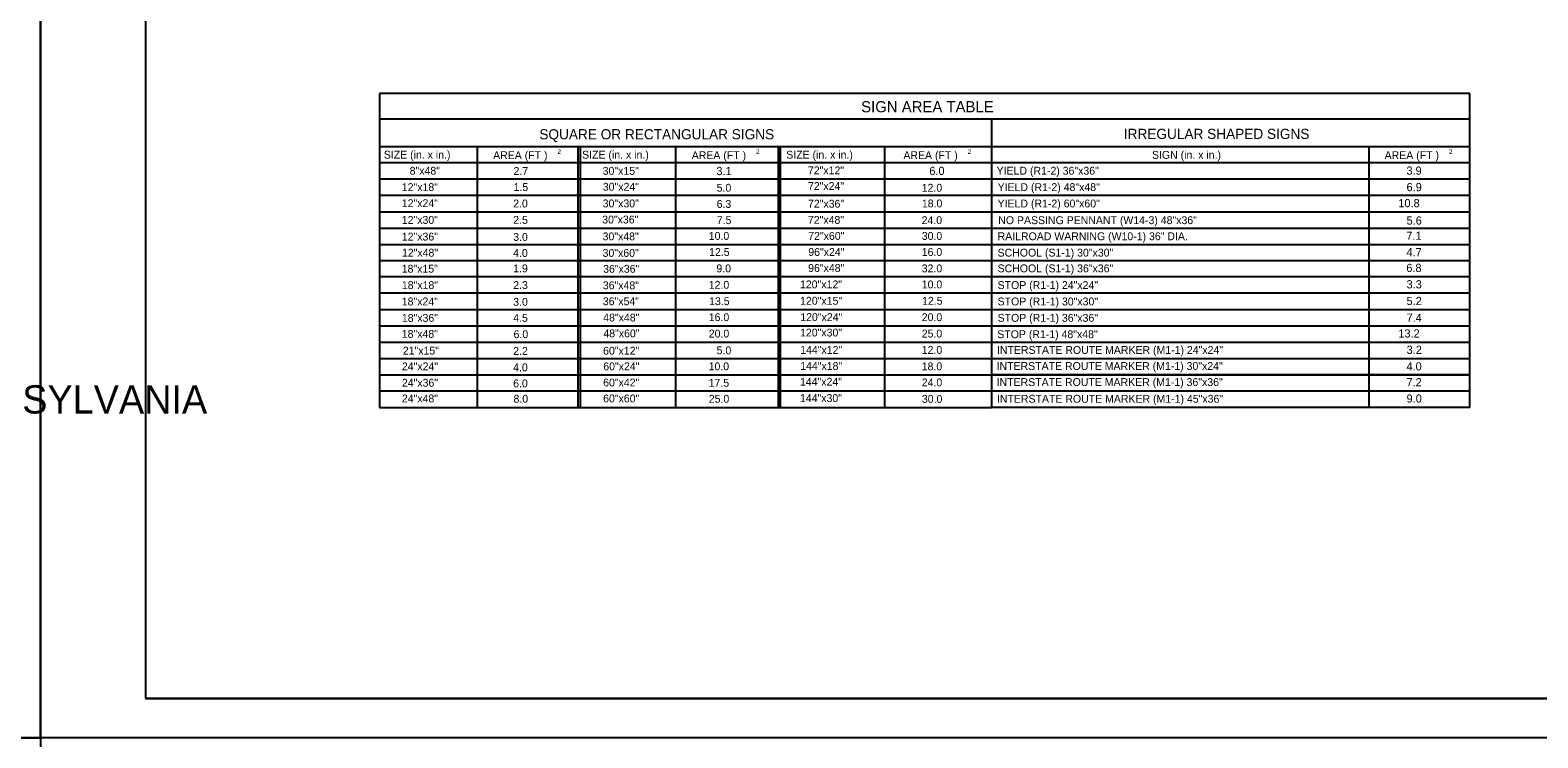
# Model space of a CAD drawing. Extents: x 644358 to 648627, y 294594 to 295782.
# Drawn here: x 646877 to 647452, y 295188 to 295458 of the extents above; entities that cross this region are included whole.
import ezdxf

# ---------------------------------------------------------------- set-up
doc = ezdxf.new("R2010")
doc.units = 0
for name, color, linetype in [('1', 7, 'Continuous'), ('2', 7, 'Continuous'), ('4', 7, 'Continuous'), ('PLT-BNDY', 7, 'Continuous')]:
    doc.layers.add(name, color=color, linetype=linetype)

msp = doc.modelspace()

# ---------------------------------------------------------------- linework, layer by layer
at = {"layer": '1'}
for p, q in [((646921.31, 295766.63), (646921.31, 295202.63)), ((647707.31, 295202.63), (646921.31, 295202.63)), ((646921.31, 295202.63), (647507.31, 295202.63))]:
    msp.add_line(p, q, dxfattribs=at)
at = {"layer": '2'}
for p, q in [((647010.62, 295433.46), (647010.62, 295313.71)), ((647426.37, 295433.46), (647010.62, 295433.46)), ((647426.37, 295313.71), (647426.37, 295433.46)), ((647426.37, 295423.59), (647010.62, 295423.59)), ((647243.99, 295423.59), (647243.99, 295313.71)), ((647010.62, 295413.21), (647426.37, 295413.21)), ((647047.87, 295413.21), (647047.87, 295313.71)), ((647086.24, 295413.21), (647086.24, 295313.71)), ((647087.12, 295413.21), (647087.12, 295313.71)), ((647123.41, 295413.21), (647123.41, 295313.71)), ((647162.62, 295413.21), (647162.62, 295313.71)), ((647163.37, 295413.21), (647163.37, 295313.71)), ((647203.12, 295413.21), (647203.12, 295313.71)), ((647387.99, 295313.71), (647387.99, 295413.21)), ((647010.62, 295407.09), (647426.37, 295407.09)), ((647010.62, 295400.84), (647426.37, 295400.84)), ((647010.62, 295394.59), (647426.37, 295394.59)), ((647010.62, 295388.34), (647426.37, 295388.34)), ((647010.62, 295382.09), (647426.37, 295382.09)), ((647010.62, 295375.84), (647426.37, 295375.84)), ((647010.62, 295369.71), (647426.37, 295369.71)), ((647010.62, 295363.59), (647426.37, 295363.59)), ((647010.62, 295357.34), (647426.37, 295357.34)), ((647010.62, 295351.09), (647426.37, 295351.09)), ((647010.62, 295344.84), (647426.37, 295344.84)), ((647010.62, 295338.59), (647426.37, 295338.59)), ((647010.62, 295332.34), (647426.37, 295332.34)), ((647243.99, 295332.34), (647426.37, 295332.34)), ((647010.62, 295326.09), (647426.37, 295326.09)), ((647426.37, 295326.09), (647243.99, 295326.09)), ((647010.62, 295319.96), (647426.37, 295319.96)), ((647010.62, 295313.71), (647243.99, 295313.71)), ((647426.37, 295313.71), (647243.99, 295313.71))]:
    msp.add_line(p, q, dxfattribs=at)
at = {"layer": '4'}
for p, q in [((647065.07, 295327.59), (647065.07, 295327.59)), ((647065.07, 295321.34), (647065.07, 295321.34)), ((647065.07, 295315.09), (647065.07, 295315.09))]:
    msp.add_line(p, q, dxfattribs=at)
at = {"layer": 'PLT-BNDY'}
for points in [[(646040.31, 295781.63), (646881.31, 295781.63), (646881.31, 295187.63), (646040.31, 295187.63)], [(646881.31, 295781.63), (647722.31, 295781.63), (647722.31, 295187.63), (646881.31, 295187.63)], [(646040.31, 295187.63), (646881.31, 295187.63), (646881.31, 294593.63), (646040.31, 294593.63)]]:
    msp.add_lwpolyline(points, close=True, dxfattribs=at)

# ---------------------------------------------------------------- texts
at = {"layer": '1'}
msp.add_text('COMMONWEALTH OF PENNSYLVANIA', height=10.7828, dxfattribs=at).set_placement((646678.9, 295311.36))
at = {"layer": '4'}
for s, height, p in [('SIGN AREA TABLE', 4.25, (647194.24, 295426.26)), ('SQUARE OR RECTANGULAR SIGNS', 3.8872, (647071.54, 295415.94)), ('IRREGULAR SHAPED SIGNS', 3.8872, (647294.39, 295416.09)), ('SIZE (in. x in.)', 3, (647012.24, 295408.59)), ('AREA (FT )', 3, (647053.91, 295408.39)), ('2', 1.8, (647078.4, 295410.35)), ('SIZE (in. x in.)', 3, (647087.85, 295408.59)), ('AREA (FT )', 3, (647129.64, 295408.39)), ('2', 1.8, (647154.13, 295410.35)), ('SIZE (in. x in.)', 3, (647165.67, 295408.59)), ('AREA (FT )', 3, (647210.34, 295408.39)), ('2', 1.8, (647234.83, 295410.35)), ('SIGN (in. x in.)', 3, (647305.13, 295408.52)), ('AREA (FT )', 3, (647393.85, 295408.39)), ('2', 1.8, (647418.34, 295410.35)), ('72"x12"', 3, (647173.93, 295402.6)), ('YIELD (R1-2) 36"x36" ', 3, (647245.89, 295402.47)), ('3.9', 3.125, (647402.16, 295402.46)), ('8"x48"', 3, (647022.09, 295402.46)), ('2.7', 3, (647061.68, 295402.35)), ('30"x15"', 3, (647095.68, 295402.42)), ('3.1', 3.125, (647139.04, 295402.3)), ('6.0', 3.125, (647220.23, 295402.35)), ('12"x18"', 3, (647019.09, 295396.21)), ('1.5', 3, (647061.7, 295396.24)), ('30"x24"', 3, (647095.74, 295396.35)), ('5.0', 3, (647139.14, 295395.97)), ('72"x24"', 3, (647173.95, 295396.63)), ('12.0', 3, (647217.34, 295395.97)), ('YIELD (R1-2) 48"x48" ', 3, (647246.27, 295396.22)), ('6.9', 3.125, (647402.19, 295396.17)), ('12"x24"', 3, (647019.09, 295390.09)), ('2.0', 3, (647061.57, 295389.97)), ('30"x30"', 3, (647095.69, 295390)), ('6.3', 3, (647139.14, 295389.8)), ('72"x36"', 3, (647173.97, 295389.89)), ('18.0', 3, (647217.39, 295389.98)), ('YIELD (R1-2) 60"x60" ', 3, (647246.27, 295389.97)), ('10.8', 3.125, (647399.07, 295390.05)), ('12"x30"', 3, (647019.09, 295383.71)), ('2.5', 3, (647061.58, 295383.73)), ('30"x36"', 3, (647095.51, 295383.85)), ('7.5', 3, (647139.18, 295383.6)), ('72"x48"', 3, (647173.94, 295383.72)), ('24.0', 3, (647217.3, 295383.6)), ('NO PASSING PENNANT (W14-3) 48"x36" ', 3, (647246.52, 295383.6)), ('5.6', 3.125, (647402.21, 295383.42)), ('12"x36"', 3, (647019.09, 295377.34)), ('3.0', 3, (647061.57, 295377.22)), ('30"x48"', 3, (647095.66, 295377.42)), ('10.0', 3, (647136.14, 295377.6)), ('72"x60"', 3, (647174.06, 295377.61)), ('30.0', 3, (647217.35, 295377.6)), ('RAILROAD WARNING (W10-1) 36" DIA.', 3, (647246.27, 295377.47)), ('7.1', 3.125, (647402.11, 295377.62)), ('12"x48"', 3, (647019.14, 295371.21)), ('4.0', 3, (647061.53, 295371.09)), ('30"x60"', 3, (647095.66, 295371.12)), ('12.5', 3, (647136.27, 295371.47)), ('96"x24"', 3, (647174.08, 295371.48)), ('16.0', 3, (647217.34, 295371.47)), ('SCHOOL (S1-1) 30"x30" ', 3, (647246.27, 295371.22)), ('4.7', 3.125, (647402.16, 295371.32)), ('18"x15"', 3, (647019.06, 295365.09)), ('1.9', 3, (647061.56, 295365.22)), ('36"x36"', 3, (647095.86, 295365.05)), ('9.0', 3, (647139.05, 295365.22)), ('96"x48"', 3, (647174.03, 295365.37)), ('32.0', 3, (647217.34, 295365.22)), ('SCHOOL (S1-1) 36"x36" ', 3, (647246.27, 295365.22)), ('6.8', 3.125, (647402.1, 295365.35)), ('18"x18"', 3, (647019.12, 295358.84)), ('2.3', 3, (647061.58, 295358.85)), ('36"x48"', 3, (647095.74, 295358.75)), ('12.0', 3, (647136.14, 295358.95)), ('120"x12"', 3, (647170.92, 295359.11)), ('10.0', 3, (647217.35, 295359.1)), ('STOP (R1-1) 24"x24" ', 3, (647246.27, 295358.85)), ('3.3', 3.125, (647402.19, 295359.08)), ('18"x24"', 3, (647019.09, 295352.59)), ('3.0', 3, (647061.57, 295352.47)), ('36"x54"', 3, (647095.74, 295352.67)), ('13.5', 3, (647136.27, 295352.7)), ('120"x15"', 3, (647170.97, 295352.86)), ('12.5', 3, (647217.47, 295352.85)), ('STOP (R1-1) 30"x30"', 3, (647246.27, 295352.6)), ('5.2', 3.125, (647402.19, 295352.72)), ('18"x36"', 3, (647019.12, 295346.34)), ('4.5', 3, (647061.58, 295346.35)), ('48"x48"', 3, (647095.89, 295346.47)), ('16.0', 3, (647136.14, 295346.6)), ('120"x24"', 3, (647171.03, 295346.62)), ('20.0', 3, (647217.35, 295346.6)), ('STOP (R1-1) 36"x36" ', 3, (647246.27, 295346.35)), ('7.4', 3.125, (647402.19, 295346.35)), ('18"x48"', 3, (647019.08, 295340.23)), ('6.0', 3, (647061.71, 295340.11)), ('48"x60"', 3, (647095.96, 295340.42)), ('20.0', 3, (647136.14, 295340.35)), ('120"x30"', 3, (647170.95, 295340.74)), ('25.0', 3, (647217.34, 295340.35)), ('STOP (R1-1) 48"x48"', 3, (647246.14, 295340.1)), ('13.2', 3.125, (647399.08, 295340.35)), ('21"x15"', 3, (647019.48, 295333.84)), ('2.2', 3, (647061.57, 295333.73)), ('60"x12"', 3, (647095.84, 295333.8)), ('5.0', 3, (647139.14, 295333.95)), ('144"x12"', 3, (647171, 295334.12)), ('12.0', 3, (647217.34, 295334.1)), ('INTERSTATE ROUTE MARKER (M1-1) 24"x24" ', 3, (647246.02, 295334.1)), ('3.2', 3.125, (647402.22, 295334.1)), ('24"x24"', 3, (647019.13, 295327.84)), ('60"x24"', 3, (647095.91, 295327.85)), ('10.0', 3, (647136.08, 295327.85)), ('144"x18"', 3, (647171, 295327.99)), ('18.0', 3, (647217.33, 295327.85)), ('INTERSTATE ROUTE MARKER (M1-1) 30"x24" ', 3, (647245.89, 295327.97)), ('4.0', 3.125, (647402.17, 295327.77)), ('4.0', 3, (647061.54, 295327.46)), ('24"x36"', 3, (647019.13, 295321.59)), ('6.0', 3, (647061.55, 295321.34)), ('60"x42"', 3, (647095.87, 295321.67)), ('17.5', 3, (647136.09, 295321.57)), ('144"x24"', 3, (647170.91, 295321.99)), ('24.0', 3, (647217.35, 295321.72)), ('INTERSTATE ROUTE MARKER (M1-1) 36"x36" ', 3, (647245.89, 295321.85)), ('7.2', 3.125, (647402.16, 295321.72)), ('24"x48"', 3, (647019.12, 295315.6)), ('8.0', 3, (647061.68, 295315.49)), ('60"x60"', 3, (647095.87, 295315.6)), ('25.0', 3, (647136.14, 295315.47)), ('144"x30"', 3, (647170.91, 295315.74)), ('30.0', 3, (647217.39, 295315.44)), ('INTERSTATE ROUTE MARKER (M1-1) 45"x36" ', 3, (647246.02, 295315.47)), ('9.0', 3.125, (647402.21, 295315.51))]:
    msp.add_text(s, height=height, dxfattribs=at).set_placement(p)

doc.saveas('drawing.dxf')
